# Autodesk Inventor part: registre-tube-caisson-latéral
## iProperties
Author: chr
Created: 2001-06
Part Number: registre-tube-caisson-latéral
Material: Par défaut
Document SubType Name: Modélisation
Designer: chr
Control State: 0
Master: False
Checked Out: False
PropertySet Name: Design Tracking Control
Shininess: 21.0
PropertySet Name: _Private Model Information
Length Units: 11269
Angle Units: 11286
Time Units: 11279
Mass Units: 11290
Length Display Precision: 3
Angle Display Precision: 2
Compacted: False
Density: 0.0
Volumn: 0.0
Area: 0.0
PropertySet Name: Model Information
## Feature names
1. Extrusion1
2. Extrusion2
